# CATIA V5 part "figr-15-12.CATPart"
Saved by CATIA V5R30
Part number: Part1
Bounding box of the stored display mesh (mm): x -50 to 50, y -32.5 to 33.5, z -52 to 1
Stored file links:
  D:\PROJECTS\CATIA V56R 2020\Resources\Parts File\c15_catia_v5_6r2020_prt\figr-15-12.CATPart
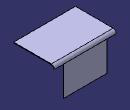
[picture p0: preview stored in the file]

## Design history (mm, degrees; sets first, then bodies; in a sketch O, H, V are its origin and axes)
SheetMetalParameters1: Thickness 1, BendRadius 4, KFactor 0.475772 {= log(min(100,max(20*SheetMetalParameters1.BendRadius,SheetMetalParameters1.Thickness)/SheetMetalParameters1.Thickness))/log(100)/2}, ReliefRadialLength 4, ReliefAxialLength 4, MinimumBendRadius 0
Body1 (main body)
  Sketch1 on xy-plane, origin (0, 0, 0), H (1, 0, 0), V (0, 1, 0)
    line L1 (-50, 32.5) -> (50, 32.5)
    line L2 (50, 32.5) -> (50, -32.5)
    line L3 (50, -32.5) -> (-50, -32.5)
    line L4 (-50, -32.5) -> (-50, 32.5)
    length L1 = 100
    length L2 = 65
    horizontal: L1 H, L3 H
    vertical: L2 V, L4 V
    symmetry: L4 L2 V, L1 L3 H
  Wall1: Thickness 1, Profile Sketch1
  d_NewWallOnEdge1: NewWallOnEdge_Edge edge [face of Wall1 | face of Wall1], NewWallOnEdge_Length 53, NewWallOnEdge_HeightLimitOffset 0, NewWallOnEdge_WidthOffset1 -15, NewWallOnEdge_WidthOffset2 -15, NewWallOnEdge_Angle 90, NewWallOnEdge_BendRadiusValue 4 {= SheetMetalParameters1.BendRadius}, NewWallOnEdge_BendTable SheetMetalParameters1, KFacteur 0.475772 {= log(min(100,max(20*d_NewWallOnEdge1.Radius,SheetMetalParameters1.Thickness)/SheetMetalParameters1.Thickness))/log(100)/2}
